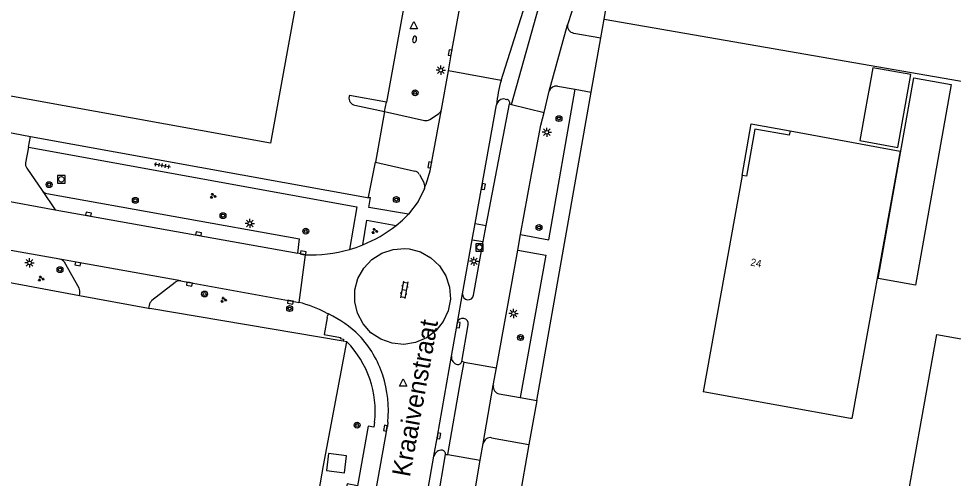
# Model space of a CAD drawing. Extents: x 130998 to 133001, y 398999 to 403002.
# Drawn here: x 132620.8 to 132747.8, y 399324.9 to 399387.3 of the extents above; entities that cross this region are included whole.
import ezdxf

# ---------------------------------------------------------------- set-up
doc = ezdxf.new("R2010")
doc.units = 0
for name, color, linetype in [('gg-afsc-hekwerk', 7, 'Continuous'), ('gg-anno-huisnummerreeks BGT', 7, 'Continuous'), ('gg-anno-openbare ruimte label', 7, 'Continuous'), ('gg-bbg-gedigitaliseerde bijgebouw', 7, 'Continuous'), ('gg-bbg-hoofdgebouw', 7, 'Continuous'), ('gg-bbg-luifel en loopbrug', 7, 'Continuous'), ('gg-bbg-onder overbouw', 7, 'Continuous'), ('gg-bbg-pand overbouw', 7, 'Continuous'), ('gg-knt-verharding', 7, 'Continuous'), ('gg-knt-verharding nz', 7, 'Continuous'), ('gt-grn-vlakafsluiter', 7, 'Continuous'), ('gt-grn-weggrens', 7, 'Continuous'), ('gt-symb-boom', 7, 'Continuous'), ('gt-symb-brandkraan', 7, 'Continuous'), ('gt-symb-groenvak', 7, 'Continuous'), ('gt-symb-klinker verharding', 7, 'Continuous'), ('gt-symb-kolk', 7, 'Continuous'), ('gt-symb-lichtmast', 7, 'Continuous'), ('gt-symb-rioolschacht', 7, 'Continuous'), ('gt-symb-tegel verharding', 7, 'Continuous'), ('gt-symb-waterafsluiter', 7, 'Continuous')]:
    doc.layers.add(name, color=color, linetype=linetype)

# ---------------------------------------------------------------- blocks, each defined once
blk = doc.blocks.new('gt0-BOOM')
at = {"layer": 'gt-symb-boom'}
for radius in [0.4, 0.2]:
    blk.add_circle((0, 0), radius, dxfattribs=at)
blk = doc.blocks.new('gt0-LMAST')
at = {"layer": 'gt-symb-lichtmast'}
for p, q in [((-0.18, 0.17), (-0.45, 0.44)), ((-0.01, 0.25), (-0.01, 0.62)), ((0.17, 0.17), (0.44, 0.44)), ((-0.26, 0), (-0.63, 0)), ((-0.18, -0.18), (-0.45, -0.45)), ((-0.01, -0.25), (-0.01, -0.63)), ((0.44, -0.45), (0.17, -0.18)), ((0.24, 0), (0.62, 0))]:
    blk.add_line(p, q, dxfattribs=at)
blk.add_circle((-0.01, 0), 0.25, dxfattribs=at)
blk = doc.blocks.new('gt0-KOLK')
at = {"layer": 'gt-symb-kolk'}
blk.add_lwpolyline([(0, 0), (0.37, 0), (0.37, 0.4), (-0.38, 0.4), (-0.38, 0), (0, 0)], dxfattribs=at)
blk = doc.blocks.new('gt0-WAFSL')
at = {"layer": 'gt-symb-waterafsluiter'}
for p, q in [((-0.5, -0.33), (0, 0.67)), ((0, 0.67), (0.5, -0.33)), ((0.5, -0.33), (-0.5, -0.33))]:
    blk.add_line(p, q, dxfattribs=at)
blk = doc.blocks.new('gt0-BR')
at = {"layer": 'gt-symb-brandkraan'}
for centre, radius, start, end in [((-0.24, 0), 0.206, 107.5669, 252.4331), ((0.6, -2.66), 3, 106.892, 107.5669), ((0, -0.69), 0.938, 73.108, 106.892), ((-0.6, -2.66), 3, 72.4331, 73.108), ((0.24, 0), 0.206, 287.567, 72.4331), ((0.6, 2.66), 3, 252.4331, 253.108), ((0, 0.69), 0.938, 253.108, 286.8921), ((-0.6, 2.66), 3, 286.8921, 287.567)]:
    blk.add_arc(centre, radius, start, end, dxfattribs=at)
blk = doc.blocks.new('gt0-TEG1')
at = {"layer": 'gt-symb-tegel verharding'}
for p, q in [((-1.12, 0), (1.12, 0)), ((-0.9, -0.25), (-0.9, 0.25)), ((-0.45, -0.25), (-0.45, 0.25)), ((0, -0.25), (0, 0.25)), ((0.45, -0.25), (0.45, 0.25)), ((0.9, -0.25), (0.9, 0.25))]:
    blk.add_line(p, q, dxfattribs=at)
blk = doc.blocks.new('gt0-GRVAK')
at = {"layer": 'gt-symb-groenvak'}
for p, q in [((-0.11, 0.19), (-0.23, 0.24)), ((-0.18, 0.15), (0.09, 0.15)), ((-0.09, 0.21), (-0.16, 0.32)), ((-0.05, 0.21), (-0.05, 0.39)), ((0, 0.21), (0.06, 0.32)), ((0.01, 0.19), (0.13, 0.24)), ((0.26, -0.05), (0.2, 0.06)), ((0.3, -0.05), (0.3, 0.13)), ((0.35, -0.05), (0.41, 0.06)), ((-0.24, -0.23), (-0.36, -0.18)), ((-0.32, -0.26), (-0.05, -0.26)), ((-0.23, -0.21), (-0.29, -0.09)), ((-0.18, -0.2), (-0.18, -0.02)), ((-0.14, -0.21), (-0.07, -0.09)), ((-0.12, -0.23), (0, -0.18)), ((0.24, -0.07), (0.12, -0.02)), ((0.17, -0.11), (0.44, -0.11)), ((0.37, -0.07), (0.49, -0.02))]:
    blk.add_line(p, q, dxfattribs=at)
blk = doc.blocks.new('gt0-RS')
at = {"layer": 'gt-symb-rioolschacht'}
blk.add_lwpolyline([(-0.5, -0.5), (0.5, -0.5), (0.5, 0.5), (-0.5, 0.5)], close=True, dxfattribs=at)
blk.add_circle((0, 0), 0.375, dxfattribs=at)
blk = doc.blocks.new('gt0-KL1')
at = {"layer": 'gt-symb-klinker verharding'}
for p, q in [((-1.15, 0.3), (1.15, 0.3)), ((-1, -0.3), (-1, 0.3)), ((-0.5, 0.3), (-0.5, 0.45)), ((0, -0.3), (0, 0.3)), ((0.5, 0.3), (0.5, 0.45)), ((1, -0.3), (1, 0.3)), ((-1.15, -0.3), (1.15, -0.3)), ((-0.5, -0.45), (-0.5, -0.3)), ((0.5, -0.45), (0.5, -0.3))]:
    blk.add_line(p, q, dxfattribs=at)

msp = doc.modelspace()

# ---------------------------------------------------------------- linework, layer by layer
at = {"layer": 'gg-afsc-hekwerk'}
for p, q in [((132700.32, 399387.3), (132702.3, 399398.59)), ((132699.87, 399384.75), (132700.32, 399387.3)), ((132700.32, 399387.3), (132790.21, 399371.65)), ((132698.57, 399377.38), (132699.87, 399384.75)), ((132691.19, 399335.46), (132698.57, 399377.38)), ((132616.77, 399352.03), (132629.04, 399349.72)), ((132629.04, 399349.72), (132629.05, 399349.72)), ((132629.05, 399349.72), (132638.42, 399348)), ((132638.42, 399348), (132638.61, 399347.96)), ((132664.89, 399343.52), (132638.61, 399347.96)), ((132665.4, 399343.43), (132664.89, 399343.52)), ((132691.19, 399335.46), (132690.12, 399329.51)), ((132690.12, 399329.51), (132687.92, 399317.24))]:
    msp.add_line(p, q, dxfattribs=at)
msp.add_lwpolyline([(132658.12, 399303.15), (132662.23, 399326.63), (132665.4, 399343.43)], dxfattribs=at)
at = {"layer": 'gg-bbg-gedigitaliseerde bijgebouw'}
msp.add_lwpolyline([(132740.25, 399369.86), (132742.01, 399379.76), (132736.83, 399380.68), (132735.07, 399370.78), (132740.25, 399369.86)], dxfattribs=at)
at = {"layer": 'gg-bbg-hoofdgebouw'}
msp.add_line((132719.09, 399366.05), (132713.8, 399336.67), dxfattribs=at)
for points in [[(132629.28, 399457.6), (132669.52, 399450.33), (132662.73, 399412.84), (132658.4, 399413.6), (132657.12, 399406.61), (132661.44, 399405.84), (132655.03, 399370.42), (132603.15, 399379.81)], [(132725.6, 399372.11), (132740.54, 399369.36), (132733.99, 399333.01), (132733.79, 399333.05), (132713.8, 399336.67)], [(132707.2, 399323.04), (132740.6, 399316.93), (132745.54, 399344.46), (132770.39, 399340), (132761.75, 399291.66), (132703.47, 399302.19)]]:
    msp.add_lwpolyline(points, dxfattribs=at)
at = {"layer": 'gg-bbg-luifel en loopbrug'}
msp.add_lwpolyline([(132742.41, 399379.29), (132747.48, 399378.39), (132742.63, 399351.14), (132737.56, 399352.05), (132742.41, 399379.29)], dxfattribs=at)
at = {"layer": 'gg-bbg-onder overbouw'}
msp.add_line((132725.6, 399372.11), (132725.49, 399371.51), dxfattribs=at)
msp.add_lwpolyline([(132725.49, 399371.51), (132720.82, 399372.35), (132719.69, 399365.96), (132719.09, 399366.05)], dxfattribs=at)
at = {"layer": 'gg-bbg-pand overbouw'}
for p, q in [((132719.09, 399366.05), (132720.33, 399373.08)), ((132720.33, 399373.08), (132725.6, 399372.11))]:
    msp.add_line(p, q, dxfattribs=at)
at = {"layer": 'gg-knt-verharding'}
for p, q in [((132675.74, 399403.5), (132670.75, 399376)), ((132686.34, 399378.96), (132690.65, 399392.5)), ((132687.77, 399375.69), (132692.18, 399391.54)), ((132696.52, 399390.17), (132695.36, 399386.52)), ((132692.88, 399377.49), (132695.36, 399386.52)), ((132696.2, 399385.4), (132699.87, 399384.75)), ((132678.25, 399375.03), (132679.18, 399380.28)), ((132686.34, 399378.96), (132679.18, 399380.28)), ((132692.17, 399374.6), (132692.88, 399377.49)), ((132694, 399378.18), (132696.4, 399377.76)), ((132696.4, 399377.76), (132698.57, 399377.38)), ((132686.89, 399376.43), (132687.11, 399376.38)), ((132666.48, 399375.61), (132670.51, 399374.73)), ((132670.51, 399374.73), (132670.75, 399376)), ((132684.3, 399359.25), (132687.5, 399375.77)), ((132687.5, 399375.77), (132687.77, 399375.69)), ((132670.51, 399374.73), (132675.94, 399373.52)), ((132676.66, 399373.65), (132677.84, 399374.44)), ((132616.85, 399372.42), (132622.38, 399371.32)), ((132622.14, 399369.87), (132622.38, 399371.32)), ((132622.38, 399371.32), (132668.42, 399363.02)), ((132622.14, 399369.87), (132621.73, 399367.78)), ((132668.31, 399363.12), (132669.28, 399367.84)), ((132669.28, 399367.84), (132674.6, 399366.65)), ((132621.9, 399367.04), (132623.97, 399364.02)), ((132675.23, 399366.18), (132675.88, 399365.02)), ((132624.61, 399363.61), (132658.95, 399357.42)), ((132668.31, 399363.12), (132668.6, 399363.07)), ((132682.43, 399357.31), (132682.82, 399359.52)), ((132682.82, 399359.52), (132684.3, 399359.25)), ((132683.92, 399357.06), (132684.3, 399359.25)), ((132658.7, 399355.51), (132658.95, 399357.42)), ((132681.11, 399349.97), (132682.43, 399357.31)), ((132682.43, 399357.31), (132683.92, 399357.06)), ((132688.6, 399355.91), (132688.97, 399358.01)), ((132682.61, 399349.78), (132683.92, 399357.06)), ((132685.71, 399339.91), (132688.6, 399355.91)), ((132659.7, 399355.28), (132658.7, 399355.51)), ((132629, 399350.75), (132627.02, 399354.26)), ((132638.9, 399349.09), (132642.05, 399351.55)), ((132629.04, 399349.72), (132629.09, 399350)), ((132680.4, 399346.05), (132681.11, 399349.97)), ((132638.52, 399348.4), (132638.42, 399348)), ((132658.43, 399348.89), (132658.88, 399348.8)), ((132662.58, 399347.39), (132662.89, 399347.24)), ((132679.59, 399341.49), (132680.4, 399346.05)), ((132680.99, 399340.76), (132681.88, 399345.76)), ((132680.88, 399338.29), (132681.3, 399340.7)), ((132681.3, 399340.7), (132680.99, 399340.76)), ((132685.28, 399337.52), (132685.71, 399339.91)), ((132679.09, 399328.14), (132680.88, 399338.29)), ((132683.91, 399329.65), (132685.28, 399337.52)), ((132686.08, 399336.38), (132688.93, 399335.86)), ((132688.93, 399335.86), (132691.19, 399335.46)), ((132670.85, 399331.72), (132670.89, 399331.94)), ((132670.95, 399332.52), (132670.89, 399331.94)), ((132683.51, 399327.37), (132683.91, 399329.65)), ((132685.05, 399330.42), (132690.12, 399329.51)), ((132675.79, 399310.86), (132678.8, 399328.14)), ((132678.8, 399328.14), (132679.09, 399328.14)), ((132679.41, 399303.78), (132683.51, 399327.37))]:
    msp.add_line(p, q, dxfattribs=at)
for points in [[(132679.18, 399380.28), (132679.61, 399382.7), (132687.26, 399424.56), (132689.84, 399438.76), (132689.9, 399439.09)], [(132688.97, 399358.01), (132692.81, 399357.28), (132696.4, 399377.76)], [(132670.75, 399376), (132665.73, 399376.91), (132665.68, 399376.76)], [(132682.82, 399359.52), (132683.74, 399364.56), (132685.72, 399375.64)], [(132688.97, 399358.01), (132690.45, 399366.19), (132691.74, 399372.88), (132692.17, 399374.6)], [(132622.14, 399369.87), (132666.72, 399361.8), (132665.72, 399355.98)], [(132675.92, 399364.29), (132675.08, 399362.53), (132673.77, 399360.78)], [(132673.77, 399360.78), (132668.38, 399361.71), (132668.6, 399363.07)], [(132626.37, 399354.67), (132614.28, 399356.82), (132597.08, 399359.91), (132589.45, 399361.3)], [(132667.55, 399356.62), (132668.08, 399359.97), (132672.06, 399359.24)], [(132672.06, 399359.24), (132672.94, 399359.98), (132673.77, 399360.78)], [(132665.72, 399355.98), (132666.64, 399356.28), (132667.55, 399356.62)], [(132666.46, 399348.88), (132666.47, 399350.49), (132666.89, 399352.05), (132667.67, 399353.46), (132668.77, 399354.64), (132670.13, 399355.5), (132671.66, 399356.01), (132673.27, 399356.13), (132673.85, 399356.07), (132675.4, 399355.65), (132676.81, 399354.86), (132677.98, 399353.76), (132678.84, 399352.39), (132679.34, 399350.86), (132679.45, 399349.25), (132679.16, 399347.67), (132678.49, 399346.2), (132677.49, 399344.94), (132676.2, 399343.97), (132674.71, 399343.34), (132673.12, 399343.1), (132671.52, 399343.25), (132670, 399343.79), (132668.66, 399344.69), (132667.58, 399345.89), (132666.83, 399347.32), (132666.46, 399348.88)], [(132688.6, 399355.91), (132692.43, 399355.2), (132688.93, 399335.86)], [(132642.81, 399351.73), (132644.02, 399351.49), (132658.43, 399348.89)], [(132662.89, 399347.24), (132662.68, 399346.82), (132662.7, 399346.72), (132662.31, 399344.42), (132664.5, 399344.04), (132664.47, 399343.9), (132664.94, 399343.82), (132664.89, 399343.52)], [(132669.16, 399332.52), (132669.05, 399331.85), (132668.27, 399332.01), (132666.83, 399323.87), (132665.43, 399324.14), (132664.62, 399319.57), (132666.01, 399319.32), (132664.15, 399308.82), (132666.68, 399308.35)], [(132666.68, 399308.35), (132667.62, 399313.56), (132670.85, 399331.72)], [(132662.62, 399325.95), (132665.04, 399325.64), (132665.33, 399327.97), (132662.9, 399328.29), (132662.62, 399325.95)], [(132674.29, 399311.06), (132674.32, 399311.36), (132677.22, 399327.93)]]:
    msp.add_lwpolyline(points, dxfattribs=at)
for centre, radius, start, end in [((132696.34, 399386.38), 0.993, 171.8408, 261.4897), ((132693.84, 399377.2), 0.997, 80.6097, 163.272), ((132666.68, 399376.59), 1.01, 170.6784, 258.6808), ((132686.73, 399375.41), 1.03, 81.3164, 167.3735), ((132687.01, 399375.89), 0.5, 346.2796, 78.4063), ((132677.28, 399375.26), 0.998, 304.5526, 346.6937), ((132676.15, 399374.45), 0.951, 257.2995, 302.8788), ((132622.71, 399367.61), 0.997, 170.2227, 215.1124), ((132674.38, 399365.71), 0.967, 29.5379, 76.8994), ((132674.98, 399364.6), 0.994, 341.9665, 24.822), ((132624.79, 399364.6), 1.01, 215.4561, 259.7172), ((132660.58, 399373.78), 18.52, 292.1185, 308.3138), ((132660.58, 399373.77), 18.51, 267.2696, 286.1225), ((132626.17, 399353.64), 1.05, 35.9032, 79.4931), ((132642.66, 399350.65), 1.09, 82.0486, 124.0287), ((132628.09, 399350.27), 1.03, 345.0391, 28.1769), ((132681.86, 399349.91), 0.756, 175.6491, 349.9691), ((132639.86, 399348.1), 1.37, 134.0321, 167.5208), ((132654.75, 399332.44), 16.88, 62.377, 75.8575), ((132655.71, 399332.54), 16.36, 46.0565, 63.9889), ((132681.13, 399345.89), 0.756, 349.7004, 167.873), ((132655.8, 399334.02), 13.44, 353.6004, 44.4563), ((132656.45, 399334.38), 14.54, 18.1021, 43.1204), ((132680.6, 399341.36), 1.02, 172.8892, 259.6889), ((132680.49, 399340.87), 0.511, 261.7438, 348.2671), ((132655.27, 399334.07), 15.76, 354.3623, 17.8566), ((132686.28, 399337.36), 1, 170.7816, 259.075), ((132684.89, 399329.43), 1, 81.0914, 167.0772), ((132678.21, 399327.71), 1.01, 81.0244, 167.2533), ((132678.28, 399328.19), 0.522, 353.769, 80.9896)]:
    msp.add_arc(centre, radius, start, end, dxfattribs=at)
at = {"layer": 'gg-knt-verharding nz'}
for p, q in [((132610.4, 399364.16), (132625.75, 399361.4)), ((132623.97, 399364.02), (132625.75, 399361.4)), ((132625.75, 399361.4), (132658.7, 399355.51)), ((132677.69, 399330.61), (132679.59, 399341.49)), ((132677.22, 399327.93), (132677.69, 399330.61))]:
    msp.add_line(p, q, dxfattribs=at)
for points in [[(132676.68, 399366.68), (132676.84, 399367.45), (132678.25, 399375.03)], [(132642.81, 399351.73), (132628.86, 399354.22), (132626.37, 399354.67)]]:
    msp.add_lwpolyline(points, dxfattribs=at)
for centre, radius, start, end in [((132706.13, 399373.56), 20.52, 164.7261, 174.1823), ((132658.41, 399371.19), 18.82, 338.5009, 346.1335)]:
    msp.add_arc(centre, radius, start, end, dxfattribs=at)
at = {"layer": 'gt-grn-vlakafsluiter'}
for p, q in [((132670.51, 399374.73), (132669.28, 399367.84)), ((132668.42, 399363.02), (132668.31, 399363.12))]:
    msp.add_line(p, q, dxfattribs=at)
at = {"layer": 'gt-grn-weggrens'}
for p, q in [((132687.77, 399375.69), (132692.17, 399374.6)), ((132659.7, 399355.28), (132658.88, 399348.8)), ((132681.3, 399340.7), (132685.71, 399339.91)), ((132679.09, 399328.14), (132683.51, 399327.37))]:
    msp.add_line(p, q, dxfattribs=at)

# ---------------------------------------------------------------- block references
at = {"layer": 'gt-symb-boom'}
for p in [(132674.65, 399377.28), (132694.2, 399373.77), (132624.93, 399364.8), (132636.64, 399362.67), (132672.11, 399362.77), (132648.55, 399360.58), (132659.8, 399358.49), (132691.49, 399358.98), (132626.41, 399353.25), (132646.05, 399349.94), (132657.61, 399347.96), (132688.98, 399344.02), (132666.77, 399332.13)]:
    msp.add_blockref('gt0-BOOM', p, dxfattribs=at)
at = {"layer": 'gt-symb-brandkraan', "rotation": 79.69002960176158}
msp.add_blockref('gt0-BR', (132674.58, 399384.53), dxfattribs=at)
at = {"layer": 'gt-symb-groenvak'}
for p in [(132647.19, 399363.26), (132669.15, 399358.49), (132623.82, 399352.02), (132648.61, 399349.16)]:
    msp.add_blockref('gt0-GRVAK', p, dxfattribs=at)
at = {"layer": 'gt-symb-klinker verharding', "rotation": -99.96151659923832}
msp.add_blockref('gt0-KL1', (132673.17, 399350.52), dxfattribs=at)
at = {"layer": 'gt-symb-kolk'}
for p, rotation in [((132679.61, 399382.7), 79.6381306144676), ((132676.84, 399367.45), 79.51469497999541), ((132683.74, 399364.56), -100.29546365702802), ((132630.25, 399360.6), -10.14027647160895), ((132645.21, 399357.92), -10.14027647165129), ((132659.42, 399355.33), -10.366322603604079), ((132628.86, 399354.22), 169.6301923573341), ((132644.02, 399351.49), 169.6301923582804), ((132657.75, 399349.02), 169.6301923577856), ((132680.34, 399345.76), -99.97572577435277), ((132670.81, 399331.69), 80.03848340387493), ((132677.7, 399330.69), -99.91074480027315)]:
    msp.add_blockref('gt0-KOLK', p, dxfattribs=dict(at, rotation=rotation))
at = {"layer": 'gt-symb-lichtmast'}
for p in [(132678.15, 399380.35), (132692.55, 399371.92), (132652.21, 399359.54), (132622.28, 399354.17), (132682.66, 399354.39), (132688.02, 399347.31)]:
    msp.add_blockref('gt0-LMAST', p, dxfattribs=at)
at = {"layer": 'gt-symb-rioolschacht'}
for p in [(132626.59, 399365.52), (132683.4, 399356.28)]:
    msp.add_blockref('gt0-RS', p, dxfattribs=at)
at = {"layer": 'gt-symb-tegel verharding', "rotation": -10.197205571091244}
msp.add_blockref('gt0-TEG1', (132640.31, 399367.41), dxfattribs=at)
at = {"layer": 'gt-symb-waterafsluiter'}
for p in [(132674.47, 399386.28), (132673.05, 399337.73)]:
    msp.add_blockref('gt0-WAFSL', p, dxfattribs=at)

# ---------------------------------------------------------------- texts
at = {"layer": 'gg-anno-huisnummerreeks BGT'}
msp.add_text('24', height=1, rotation=349.8, dxfattribs=at).set_placement((132720.16, 399353.81))
at = {"layer": 'gg-anno-openbare ruimte label'}
msp.add_text('Kraaivenstraat', height=2.5, rotation=79.7, dxfattribs=at).set_placement((132673.94, 399324.99))

doc.saveas('drawing.dxf')
